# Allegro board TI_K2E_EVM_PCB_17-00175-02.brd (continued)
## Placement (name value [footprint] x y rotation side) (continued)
C819  100nF  [C0402]  131.32 21.34 270 bottom
C820  1nF  [C0402]  106.43 19.56 0 bottom
C821  560pF  [CC0201_IPC7351_EINF]  96.39 19.43 90 bottom
C822  22pF  [C0402]  104.65 18.92 270 bottom
C823  22pF  [C0402]  98.08 18.85 90 bottom
C824  100nF  [C0402]  20.95 18.8 0 bottom
C825  10uF  [C0603]  22.61 18.67 0 bottom
C826  22uF  [C0805]  24.77 17.4 180 bottom
C827  10uF  [C0603]  142.62 17.02 270 bottom
C828  100uF  [CC1210]  28.19 16.13 90 bottom
C829  10nF  [C0402]  102.87 16.05 180 bottom
C830  10nF  [C0402]  100.08 16.05 180 bottom
C831  1nF  [C0402]  153.42 16 180 bottom
C832  10nF  [C0402]  151.89 16 180 bottom
C833  100nF  [C0402]  150.37 16 180 bottom
C834  100nF  [C0402]  139.98 15.9 180 bottom
C835  100nF  [C0402]  147.45 14.28 0 bottom
C836  100nF  [C0402]  144.4 14.61 0 bottom
C837  10uF  [C0603]  142.75 14.61 0 bottom
C838  1uF  [C0402]  144.91 11.18 180 bottom
C839  100nF  [C0402]  143.51 11.18 180 bottom
C840  100nF  [C0402]  142.11 11.18 180 bottom
C841  4.7uF  [C0603]  146.56 10.79 180 bottom
C842  4.7nF  [C0402]  62.28 9.74 270 bottom
C843  10nF  [C0402]  104.01 9.4 270 bottom
C844  33pF  [C0402]  135.13 8.57 90 bottom
C845  33pF  [C0402]  132.97 8.57 270 bottom
C846  100nF  [C0402]  127.64 8.38 90 bottom
C847  100nF  [C0402]  131.06 8.06 180 bottom
C848  220nF  [C0402]  129.54 8.06 180 bottom
C849  2.2uF  [C0402]  59.56 7.24 270 top
C850  1uF  [C0402]  127.64 6.86 90 bottom
C851  6.8pf  [C0402]  97.16 6.1 90 bottom
C852  3.3uF  [C0603]  102.54 5.59 0 bottom
C853  4.7uF  [C0603]  100.84 5.59 0 bottom
C854  10uF  [C0603]  99.14 5.59 0 bottom
C855  10uF  [C0603]  127.64 5.08 90 bottom
C856  12pF  [C0402]  105.56 4.5 270 bottom
C857  100pF  [C0402]  66.42 4.19 0 bottom
C858  2.2nF  [C0402]  64.9 4.19 0 bottom
C859  2.2nF  [C0402]  62.1 4.19 0 bottom
C860  100nF  [C0402]  126.47 105.26 0 top
C861  100nF  [C0402]  127.89 106.81 0 top
C862  100nF  [C0402]  126.47 107.29 0 top
C863  100nF  [C0402]  125.96 103.61 90 top
C864  100nF  [C0402]  127.89 104.78 0 top
C865  100nF  [C0402]  123.91 109 90 top
C866  22uF  [C0805]  123.93 99.43 270 top
C872  10pF  [C0402]  12.7 35.94 270 bottom
C874  10pF  [C0402]  12.81 130.35 90 bottom
C875  100nF  [C0402]  141.22 119 270 bottom
C876  100nF  [C0402]  139.95 126.75 90 bottom
C881  100nF  [C0402]  146.18 21.59 90 bottom
C882  10uF  [C0603]  146.18 19.81 90 bottom
C883  100nF  [C0402]  141.35 22.86 180 bottom
C884  10uF  [C0603]  139.57 23.62 180 bottom
C885  100nF  [C0402]  158 10.09 180 bottom
C886  100nF  [C0402]  171.45 10.09 180 bottom
C887  10uF  [C0603]  160.02 9.58 180 bottom
C888  100nF  [C0402]  169.93 10.09 180 bottom
C889  100nF  [C0402]  169.54 22.33 90 bottom
C890  100nF  [C0402]  169.54 20.83 90 bottom
C891  10uF  [C0603]  163.83 30.38 0 bottom
C892  100nF  [C0402]  161.81 30 0 bottom
C893  100nF  [C0402]  42.55 91.69 90 bottom
C894  100nF  [C0402]  46.99 91.95 0 top
C895  100nF  [C0402]  148.21 27.81 0 bottom
C896  10pF  [C0402]  17.18 132.85 90 bottom
CN1  TSW-103-23-T-S  [BERG_1X3]  153.37 140.97 0 top
CN2  5223957-3  [POWERMODULE_2P_5223957-3]  27.5 140.75 270 top
CN3  FTSH-105-01-F-DV-K-P-TR  [SAMTECH_FTSH-105-01-F-DV-K-P-TR]  102.11 138.43 0 top
CN4  TSW-102-23-T-S  [SAMTSW-102-22-T-S]  134.54 123.19 180 top
CN5  TSW-106-23-T-S  [SAMTEC_TSW-106-23-T-S]  125.73 114.55 90 top
CN6  TSW-103-23-T-S  [BERG_1X3]  134.37 119 0 top
CN7  BB_60x2V_S0.5mm  [BB_60X2P_20_2225X285_F]  37.93 115.24 90 top
COM1  22-23-2041  [MOL22-23-2041]  167.06 122.05 270 top
COM2  22-23-2041  [MOL22-23-2041]  158.12 122.05 270 top
CT1  1000uF  [CT7343]  61.98 26.54 180 top
CT2  680uF  [CT7343]  61.98 21.34 180 top
CT3  1000uF  [CT7343]  61.98 16.13 180 top
CT4  100uF  [CT7343]  50.01 12.7 90 top
CT5  100uF  [CT7343]  44.81 12.7 90 top
CT6  100uF  [CT7343]  86.36 10.92 270 top
CT7  100uF  [CT7343]  36.83 9.53 270 top
CT8  220uF  [C_2P_114_138X118]  110.34 36.93 90 bottom
CVDD  Test Point  [TP365X205]  73.15 22.35 0 top
CVDD1  Test Point  [TP-S40]  83.95 22.73 0 top
D1  PMEG1020EH  [DIODE_2P_146_106X61_ANODE2]  126.87 146.05 90 top
D2  PMEG1020EH  [DIODE_2P_146_106X61_ANODE2]  126.87 143.76 90 top
D3  KPA-1606EC  [LED_2P_KPA-1606EC]  178.9 129.12 270 top
D4  KPA-1606QBC-D  [LED_2P_KPA-1606QBC-D]  178.9 125.84 270 top
D5  KP-1608EC  [LED_0603]  179.2 112.9 270 top
D6  KP-1608MGC  [LED_0603]  179.2 109.81 90 top
D7  GREEN  [LED603-35X45-REV]  177.25 109.6 270 top
D8  GREEN  [LED603-35X45-REV]  175.14 109.6 270 top
D9  GREEN  [LED603-35X45-REV]  173.02 109.6 270 top
D10  LED  [LED_LTST-C171]  48.51 25.53 180 top
D11  B340A-13-F  [DIODE_2P_158_197X110]  13.97 17.91 90 top
D12  SMBJ12A  [DIO_DO214AA_SMB]  32.13 9.14 90 top
D13  TPD4S012DRYR  [SON_6P_20_59X39]  167.77 135.94 270 bottom
D14  TPD4S012DRYR  [SON_6P_20_59X39]  166.62 100.72 270 bottom
D15  B340A-13-F  [DIODE_2P_158_197X110]  62.38 32.69 0 bottom
DBG_D1  KPBA-3010ESGC  [LED_2P_KPBA-3010ESGC]  178.51 121.69 90 top
DBG_D2  SML-LX0402USBC-TR  [LED_SML-LX0402]  179.2 117.99 90 top
DBG_D3  SML-LX0402USBC-TR  [LED_SML-LX0402]  179.2 115.62 90 top
DIMM1  2013289-1_DDR3-SODIMM_204P  [TYCO2013289-2_DDR3]  97.54 92.57 90 top
EEPROM1  M24M01-RMN6TP  [SOIC_8P_50_193X236]  117.22 75.31 270 bottom
EMU1  BB_60V_S0.5mm  [BB_30X2P_20_838X285_F]  96.77 116.72 270 top
ESD1  -  [AMC-ESD-B]  160 146.15 0 top
F1  RGEF600-2  [PTC_RUEF300]  25.7 5.48 90 top
FAN1  22-23-2041  [MOL22-23-2041]  83.14 29.58 0 top
FB1  220_100MHz  [L0805]  111.18 138.46 90 top
FB2  120_100MHz  [L0402]  129.46 130.18 90 top
FB3  120_100MHz  [L0402]  108.2 122.66 270 top
FB4  220_100MHz  [L0805]  168.53 93.47 90 top
FB5  220_100MHz  [L0805]  142.75 92.33 270 top
FB6  30_100MHz  [L0805]  174.5 50.04 90 top
FB7  120_100MHz  [L0402]  24.13 37.97 270 top
FB8  120_100MHz  [L0402]  176.02 32.51 0 top
FB9  120_100MHz  [L0402]  29.72 29.34 0 top
FB10  120_100MHz  [L0402]  42.93 28.32 180 top
FB11  120_100MHz  [L0402]  35.69 26.92 90 top
FB12  30_100MHz  [L0805]  25.45 24.84 90 top
FB13  120_100MHz  [L0402]  172.25 141.48 180 bottom
FB14  220_100MHz  [L0805]  168.78 132.33 270 bottom
FB15  BLM31PG500SN1L  [INDC1206]  162.1 107.42 0 bottom
FB16  120_100MHz  [L0402]  176.82 106.9 0 bottom
FB17  0.47uF  [FIL_NFM21PC]  163.45 98.93 180 bottom
FB18  0.47uF  [FIL_NFM21PC]  162.69 94.49 180 bottom
FB19  0.47uF  [FIL_NFM21PC]  148.65 87.63 90 bottom
FB20  120_100MHz  [L0402]  61.34 85.19 0 bottom
FB21  470_100MHz  [L0402]  75.31 83.69 90 bottom
FB22  120_100MHz  [L0402]  71.88 82.68 90 bottom
FB23  120_100MHz  [L0402]  32 81.53 90 bottom
FB24  470_100MHz  [L0402]  38.76 80.14 90 bottom
FB25  120_100MHz  [L0402]  32.51 76.2 90 bottom
FB26  470_100MHz  [L0402]  32.61 70.76 270 bottom
FB27  120_100MHz  [L0402]  31.88 65.53 90 bottom
FB28  100_100MHz  [L0402]  80.9 62.87 0 bottom
FB29  120 OHM_100Mhz  [L0402]  33.15 59.44 270 bottom
FB30  120_100MHz  [L0402]  38.1 58.24 180 bottom
FB31  120 OHM_100Mhz  [L0402]  33.15 52.53 270 bottom
FB32  120_100MHz  [L0402]  148.82 38.33 270 bottom
FB33  120_100MHz  [L0402]  34.92 26.92 90 bottom
FB34  120_100MHz  [L0402]  151.38 20.83 0 bottom
FB35  120_100MHz  [L0402]  145.92 14.61 270 bottom
FM1  Fiducial  [FIDUCIAL]  21.98 36.32 0 top
FM2  Fiducial  [FIDUCIAL]  21.98 36.32 180 bottom
FM3  Fiducial  [FIDUCIAL]  147.78 4.98 0 top
FM4  Fiducial  [FIDUCIAL]  147.78 4.98 180 bottom
FM5  Fiducial  [FIDUCIAL]  157.66 136.8 0 top
FM6  Fiducial  [FIDUCIAL]  157.66 136.8 180 bottom
GND1  Test Point  [TP-S40]  24.51 27.56 0 top
GND2  Test Point  [TP-S40]  155.57 45.97 0 top
GND3  Test Point  [TP-S40]  152.27 129.41 0 top
GND4  Test Point  [TP-S40]  45.34 118.62 0 top
GNDC  Test Point  [TP365X205]  50.16 19.56 0 top
H1  -  [H35-NPTH]  157.1 132.72 0 top
H2  -  [H35-NPTH]  29.34 132.33 0 top
H3  -  [H35-NPTH]  42.42 24.64 0 top
H4  H107x17-NPTH  [H107X17-NPTH]  159 4.8 0 top
H5  -  [H35-NPTH]  168.78 4.19 0 top
H6  -  [H27P35-MTH]  176.85 3.25 0 top
J1  54819-0519  [MOL54819-0519]  171.8 134.91 90 top
J2  ATCA  [ATCA_160P_384312]  7.9 122.85 270 top
J3  54819-0519  [MOL54819-0519]  171.8 99.7 90 top
J4  ATCA  [ATCA_160P_384312]  7.9 97.85 270 top
J5  HEADER 10X2 CTI-20  [SAMFTR-110-03-G-D-LC]  159.35 90.3 270 top
J6  KMMXAB10SMT4SB30  [KYCON_KMMXAB10SMT4SB30]  175.07 56.19 90 top
J7  USB3.0_9H  [USB_9P_UEA1112C-4HK1-4H]  168.62 41.13 90 top
J8  280371-2  [TE_280371-2]  19 25.78 270 top
J9  XMH-TRJG17020AENL  [XMULTIPLE_XMH-TRJG17020AENL]  165.09 16.75 90 top
J10  0678005001  [MOL67800-5005]  36.64 19.96 0 top
J11  PJ-044BH  [CUI_PJ-044BH]  18.38 4.11 180 top
L1  LQM2HPN2R2MJ0L  [IND1008]  139.7 78.36 180 top
L2  1.2uH,11.1A  [IND_XAL5030-222MEB]  148.11 70.01 180 top
L3  ACM2012-900-2P-TL  [ACM2012]  167.89 63 0 top
L4  ACM2012-900-2P-TL  [ACM2012]  167.89 61.1 0 top
L5  ACM2012-900-2P-TL  [ACM2012]  167.89 59.19 0 top
L6  2.2uH,5A  [IND_VLCF5020T]  150.57 57.62 270 top
L7  ACM2012-900-2P-TL  [ACM2012]  158.5 41.21 0 bottom
L8  ACM2012-900-2P-TL  [ACM2012]  158.5 43.31 0 bottom
L9  ACM2012-900-2P-TL  [ACM2012]  158.5 39.12 0 bottom
L10  2.2uH,5A  [IND_VLCF5020T]  109.88 18.16 0 top
L11  2.2uH,5A  [IND_VLCF5020T]  91.95 16.89 0 top
L12  220nH,30.7A  [IND_IHLP3232DZERR47M01]  73.15 15.16 90 top
L13  3.3uH,4A  [IND_VLC5045T-100M]  109.88 7.57 180 top
L14  3.3uH,4A  [IND_VLC5045T-100M]  92.2 7.49 180 top
LCD1  NHD-C12832A1Z-FSB-FBW-3V3  [LCD_17P_NHD-C12832A1Z]  65.91 134.11 180 top
NOR1  N25Q128A11ESF40F  [SOIC127P1032_16]  144.17 46.2 0 top
NOREF  -  []  0 3.81 0 top
NOREF#2  -  []  176.85 3.25 0 top
NOREF#3  -  []  157.1 132.72 90 top
NOREF#4  -  []  6.7 144.2 0 top
NOREF#5  -  []  0 3.81 0 top
NOREF#6  -  []  180.6 1.1 90 top
NOREF#7  -  []  0 36.75 0 top
NOREF#8  -  []  158 0 90 top
NOREF#9  -  []  29.34 132.33 90 top
NOREF#10  -  []  122.33 179.27 180 bottom
OSC1  32.768KHz  [OSCCC200X250X70-4N]  152.4 132.59 180 top
PMBUS1  TSW-105-23-T-S  [HD_5X1P_100_D]  130.05 120.14 90 top
Q1  MCP9700AT-E/LT  [SC-70_5P]  114.55 139.92 0 top
Q2  TLV1117-33CDCY  [SOT-223]  125.73 137.54 0 top
Q3  2N3904  [SOT-23]  174.88 128.14 90 top
Q4  2N3904  [SOT-23]  174.75 123.19 90 top
Q5  2N3904  [SOT-23]  174.75 118.36 90 top
Q6  2N3904  [SOT-23]  174.75 113.79 90 top
Q7  NTA4153N  [SOT416_3P]  170.81 109.56 0 top
Q8  NTA4153N  [SOT416_3P]  166.75 109.56 0 top
Q9  PBSS5120T,215  [SOT23]  44.83 33.53 90 top
Q10  APL431LBAI-TRG  [SOT-23]  67.58 141.09 0 bottom
Q11  2N3904  [SOT-23]  174.88 128.14 270 bottom
Q12  2N3904  [SOT-23]  174.75 123.19 270 bottom
Q13  2N3904  [SOT-23]  174.75 118.36 270 bottom
Q14  2N3904  [SOT-23]  174.75 113.79 270 bottom
Q15  TPS73701DRBT  [QFN_8P_26_118X118]  145.16 24.51 90 bottom
R1  10M  [R1206]  153.03 145.29 270 top
R2  10M  [R1206]  38.48 145.29 90 top
R3  0E  [R0402]  164.47 143.51 90 top
R4  0E  [R0402]  163.07 143.51 90 top
R5  33K  [R0402]  149.86 141.99 0 top
R6  4.7K  [R0402]  162.56 140.46 270 top
R7  0E  [R0402]  149.86 139.45 0 top
R8  33K  [R0402]  149.86 137.92 0 top
R9  10K  [R0402]  153.37 136.96 270 top
R10  10K  [R0402]  149.86 136.4 180 top
R11  0E  [R0402]  120.02 135.51 90 top
R12  0E  [R0402]  118.49 135.51 90 top
R13  10K  [R0402]  116.59 135.51 270 top
R14  10K  [R0402]  115.06 135.51 270 top
R15  10K  [R0402]  113.54 135.51 270 top
R16  0E  [R0402]  149.86 135 0 top
R17  0E  [R0402]  121.67 134.62 0 top
R18  3K  [RC0201_IPC7351_EINF]  109.22 133.76 180 top
R19  0E  [R0402]  121.41 133.22 180 top
R20  0E  [R0402]  105.97 132.97 0 top
R21  1.3K  [R0402]  109.22 132.21 180 top
R22  22E  [R0402]  149.61 131.7 0 top
R23  0E  [R0402]  121.41 131.7 180 top
R24  10K  [R0402]  105.97 131.58 0 top
R25  0E  [R0402]  109.22 130.68 180 top
R26  0E  [R0402]  121.41 130.18 0 top
R27  510E  [R0402]  173.23 130.05 0 top
R28  10K  [R0402]  149.61 130.05 180 top
R29  0E  [R0402]  109.22 129.29 180 top
R30  0E  [R0402]  121.41 128.65 180 top
R31  4.7K  [R0402]  102.62 128.52 180 top
R32  49.9E  [R0402]  177.42 127.87 270 top
R33  90.9K  [R0402]  109.22 127.76 180 top
R34  0E  [R0402]  31.81 127.76 180 top
R35  4.7K  [R0402]  29.84 127.76 180 top
R36  0E  [R0402]  121.41 127.13 180 top
R37  10E  [R0402]  102.62 127.13 180 top
R38  10K  [R0402]  138.19 126.67 270 top
R39  0E  [R0402]  136.14 126.62 90 top
R40  0E  [R0402]  134.62 126.62 90 top
R41  0E  [R0402]  109.22 126.36 180 top
R42  0E  [R0402]  30.86 126.36 180 top
R43  0E  [R0402]  121.41 125.73 0 top
R44  4.7K  [R0402]  102.62 125.73 180 top
R45  100E  [R0402]  90.83 125.35 0 top
R46  100E  [R0402]  88.27 125.35 180 top
R47  120E  [R0402]  177.55 125.22 90 top
R48  510E  [R0402]  173.1 124.97 0 top
R49  0E  [R0402]  109.22 124.97 180 top
R50  33E  [R0402]  121.41 124.33 0 top
R51  10E  [R0402]  102.62 124.33 180 top
R52  10E  [R0402]  90.81 123.95 0 top
R53  4.7K  [R0402]  88.27 123.95 180 top
R54  22E  [R0402]  43.75 122.99 0 top
R55  0E  [R0402]  121.92 122.66 270 top
R56  0E  [R0402]  120.4 122.66 270 top
R57  0E  [R0402]  119 122.66 270 top
R58  0E  [R0402]  117.47 122.66 90 top
R59  0E  [R0402]  115.98 122.66 90 top
R60  0E  [R0402]  114.4 122.66 270 top
R61  0E  [R0402]  112.9 122.66 270 top
R62  0E  [R0402]  111.46 122.66 270 top
R63  0E  [R0402]  109.91 122.66 270 top
R64  4.7K  [R0402]  102.87 122.56 0 top
R65  10E  [R0402]  90.81 122.56 0 top
R66  4.7K  [R0402]  88.27 122.56 180 top
R67  0E  [R0402]  102.87 121.16 0 top
R68  0E  [R0402]  90.81 121.16 0 top
R69  49.9E  [R0402]  176.66 120.14 180 top
R70  510E  [R0402]  173.1 120.14 0 top
R71  120E  [R0402]  177.55 118.54 180 top
R72  10K  [R0402]  142.62 116.97 270 top
R73  120E  [R0402]  177.42 116.17 180 top
R74  1K  [R0402]  68.96 116.15 0 top
R75  510E  [R0402]  173.1 115.44 0 top
R76  2.2K  [R0402]  140.72 115.06 0 top
R77  2.2K  [R0402]  138.68 115.06 0 top
R78  2.2K  [R0402]  136.53 115.06 180 top
R79  22E  [R0402]  145.8 113.92 270 top
R81  22E  [R0402]  153.54 113.92 270 top
R82  22E  [R0402]  151.89 113.92 270 top
R83  22E  [R0402]  150.37 113.92 270 top
R84  470E  [R0402]  148.84 113.92 90 top
R85  470E  [R0402]  147.37 113.92 90 top
R87  2.2K  [R0402]  133.73 113.92 180 top
R88  4.7K  [R0402]  61.85 114.02 180 top
R89  120E  [R0402]  177.42 113.65 180 top
R90  2.2K  [R0402]  140.72 113.54 180 top
R91  2.2K  [R0402]  138.68 113.54 180 top
R92  2.2K  [R0402]  136.53 113.54 0 top
R93  0E  [R0402]  68.89 113.23 180 top
R94  0E  [R0402]  80.64 112.89 90 top
R95  4.7K  [R0402]  61.85 112.62 0 top
R96  2.2K  [R0402]  133.73 112.39 0 top
R97  10K  [R0402]  155.96 111.25 180 top
R98  470E  [R0402]  133.73 110.87 180 top
R99  4.7K  [R0402]  61.5 110.11 90 top
R100  4.7K  [R0402]  102.36 109.97 0 top
R101  10K  [R0402]  155.96 109.73 180 top
R102  470E  [R0402]  133.73 109.35 180 top
R103  2.2K  [R0402]  168.78 108.31 270 top
R104  2.2K  [R0402]  164.72 108.31 270 top
R105  47E  [R0402]  155.96 108.2 0 top
R106  470E  [R0402]  133.73 107.7 180 top
R107  470E  [R0402]  133.73 106.17 180 top
R108  0E  [R0402]  67.06 104.78 270 top
R109  4.7K  [R0402]  93.98 104.65 90 top
R110  10K  [R0402]  133.73 104.39 180 top
R111  1K  [R0402]  131.57 104.39 0 top
R112  0E  [R0402]  85.12 101.15 90 bottom
R113  10K  [R0402]  81.89 103.63 270 top
R114  10K  [R0402]  162.43 103 0 top
R115  470E  [R0402]  120.76 101.15 270 top
R116  470E  [R0402]  120.75 103 270 top
R117  470E  [R0402]  119.35 103 270 top
R118  10K  [R0402]  117.96 103 270 top
R119  470E  [R0402]  116.56 103 270 top
R120  470E  [R0402]  115.16 103 270 top
R121  470E  [R0402]  113.77 103 270 top
R122  0E  [R0402]  112.37 103 270 top
R123  0E  [R0402]  110.97 103 270 top
R124  470E  [R0402]  109.58 103 270 top
R125  10K  [R0402]  133.73 102.74 180 top
R126  1K  [R0402]  131.57 102.74 0 top
R127  4.7K  [R0402]  99.69 102.62 90 top
R128  10E  [R0402]  98.17 102.62 270 top
R129  10E  [R0402]  96.77 102.62 90 top
R130  10E  [R0402]  95.38 102.62 90 top
R131  10E  [R0402]  93.98 102.62 90 top
R132  10E  [R0402]  92.46 102.62 270 top
R133  499E  [R0603]  65.15 102.11 180 top
R134  402E  [R0603]  85.32 101.85 180 top
R135  0E  [R0402]  77.95 101.6 270 top
R136  10K  [R0402]  63.5 101.6 90 top
R137  10K  [R0402]  61.98 101.6 90 top
R138  0E  [R0402]  59.94 101.6 270 top
R139  10K  [R0402]  81.89 101.47 90 top
R140  22E  [R0402]  162.43 101.35 0 top
R141  10K  [R0402]  133.73 101.09 180 top
R142  1K  [R0402]  131.57 101.09 0 top
R143  10E  [R0402]  98.04 100.33 90 top
R144  10E  [R0402]  96.65 100.33 90 top
R145  10E  [R0402]  95.25 100.33 90 top
R146  10E  [R0402]  93.85 100.33 270 top
R147  10E  [R0402]  92.46 100.33 90 top
R148  10K  [R0402]  133.73 99.44 180 top
R149  1K  [R0402]  131.57 99.44 0 top
R150  0E  [R0402]  77.72 99.06 0 top
R151  0E  [R0402]  59.69 98.09 0 top
R152  1K  [R0402]  133.73 97.79 0 top
R153  1K  [R0402]  131.57 97.79 0 top
R154  0E  [R0402]  77.7 97.66 0 top
R155  3.16K  [R0402]  75.54 97.66 180 top
R156  1.5K  [R0603]  155.83 97.16 0 top
R157  0E  [R0402]  59.69 96.52 0 top
R158  1K  [R0402]  133.73 96.14 0 top
R159  1K  [R0402]  131.57 96.14 0 top
R160  49.9E  [R0402]  77.7 96.14 180 top
R161  5.6K  [R0402]  75.54 96.14 0 top
R162  150K  [R0402]  168.15 95.45 180 top
R163  0E  [R0402]  59.69 94.74 0 top
R164  0E  [R0402]  59.69 93.13 0 top
R165  0E  [R0402]  44.96 92.71 270 top
R166  10K  [R0402]  150.88 91.62 270 top
R167  0E  [R0402]  59.69 91.61 0 top
R168  1K  [R0402]  138.51 91.59 270 top
R169  1K  [R0402]  137.03 91.59 270 top
R170  47E  [R0402]  135.38 91.57 90 top
R171  49.9E  [R0402]  77.7 91.57 180 top
R172  1K  [R0402]  44.96 90.68 270 top
R173  0E  [RC0201_IPC7351_EINF]  46.74 86.23 180 top
R174  0E  [RC0201_IPC7351_EINF]  46.74 85.09 180 top
R175  1K  [R0402]  138.51 89.43 90 top
R176  1K  [R0402]  137.03 89.43 90 top
R177  0E  [R0402]  79.92 88.25 90 top
R178  0E  [R0402]  78.49 88.25 90 top
R179  10K  [R0402]  170.36 87.9 0 top
R180  100K  [R0402]  145.54 86.84 180 top
R181  100E  [R0402]  170.36 86.37 180 top
R182  4.7K  [R0402]  53.72 86.36 90 top
R183  4.7K  [R0402]  52.32 86.36 90 top
R184  4.7K  [R0402]  50.8 86.36 90 top
R185  0E  [R0402]  144.15 84.58 180 top
R186  0E  [R0402]  19.05 84.33 270 top
R187  0E  [R0402]  17.4 84.33 270 top
R188  4.7K  [R0402]  15.88 84.33 90 top
R189  0E  [R0402]  14.35 84.33 270 top
R190  0E  [R0402]  12.7 84.33 270 top
R191  2.49K  [R0402]  138.94 83.95 180 top
R192  10K  [R0402]  138.94 82.55 180 top
R193  4.7K  [R0402]  13.21 82.17 180 top
R194  0E  [R0402]  149.35 81.46 90 top
R195  10K  [R0402]  138.94 81.15 180 top
R196  100K  [R0402]  147.57 80.9 180 top
R197  4.7K  [R0402]  22.99 80.77 180 top
R198  4.7K  [R0402]  13.21 80.77 180 top
R199  10.2K  [R0402]  147.57 79.5 180 top
R200  4.7K  [R0402]  22.99 79.38 180 top
R201  4.7K  [R0402]  13.21 79.38 180 top
R202  0E  [R0402]  147.45 77.72 90 top
R203  2.49K  [R0402]  146.05 77.72 270 top
R204  8.87K  [R0402]  157.25 75.47 0 top
R205  10K  [R0402]  168.38 75.28 0 top
R206  0E  [RC0201_IPC7351_EINF]  81.71 75.16 0 top
R207  10E  [R0402]  150.29 74.8 270 top
R208  768E  [R0603]  154.11 74.12 270 top
R209  10K  [R0402]  157.25 73.94 180 top
R210  0E  [RC0201_IPC7351_EINF]  81.71 73.89 0 top
R211  100E  [R0402]  168.38 73.75 180 top
R212  68.1K  [R0603]  156.92 66.85 270 top
R213  10K  [R0402]  154.6 66.85 270 top
R214  0E  [RC0201_IPC7351_EINF]  80.29 65.28 0 top
R215  10K  [R0402]  144.18 60.78 90 top
R216  53.6K  [R0402]  141.3 60.53 0 top
R217  2.2K  [R0402]  144.3 53.87 180 top
R218  10K  [R0402]  142.04 53.75 0 top
R219  53.6K  [R0402]  140 53.75 180 top
R220  0E  [R0402]  161.66 53.25 0 top
R221  10E  [R0402]  147.6 53.11 90 top
R222  4.7K  [R0402]  163.47 52.79 270 top
R223  0E  [R0402]  160.71 46.4 0 top
R224  10E  [R0402]  60.2 42.75 270 top
R225  10E  [R0402]  58.67 42.75 90 top
R226  10E  [R0402]  57.15 42.75 270 top
R227  10E  [R0402]  60.2 40.59 270 top
R228  10E  [R0402]  58.67 40.59 270 top
R229  10E  [R0402]  57.15 40.55 270 top
R230  1K  [R0402]  54.61 36.45 270 top
R231  4.7K  [R0402]  44.83 36.45 270 top
R232  22E  [R0402]  81.79 36.3 270 top
R233  22E  [R0402]  80.39 36.3 270 top
R234  22E  [R0402]  78.99 36.3 90 top
R235  22E  [R0402]  77.6 36.3 90 top
R236  0E  [RC0201_IPC7351_EINF]  92.71 36.3 270 top
R237  0E  [RC0201_IPC7351_EINF]  90.12 36.3 270 top
R238  0E  [R0402]  88.82 36.3 90 top
R239  4.7K  [R0402]  87.43 36.3 270 top
R240  4.7K  [R0402]  86.03 36.3 270 top
R241  4.7K  [R0402]  84.63 36.3 90 top
R242  4.7K  [R0402]  83.24 36.3 270 top
R243  0E  [R0402]  91.41 36.27 90 top
R244  4.7K  [R0402]  93.93 36.22 270 top
R245  4.7K  [R0402]  154.2 34.45 90 top
R246  0E  [R0402]  152.76 34.45 270 top
R247  4.7K  [R0402]  94.27 33.07 180 top
R248  100E  [R0402]  172.72 32.39 270 top
R249  100E  [R0402]  164.34 32.38 270 top
R250  6.04K  [R0402]  26.8 32.38 180 top
R251  4.7K  [R0402]  94.27 31.67 180 top
R252  4.7K  [R0402]  94.27 30.28 180 top
R253  4.7K  [R0402]  94.27 28.88 180 top
R254  2.2K  [R0402]  48.51 23.62 0 top
R255  0E  [R0402]  100.2 21.87 270 top
R256  2.7K  [R0402]  103.97 20.32 0 top
R257  2.49K  [R0402]  98.08 20.24 0 top
R258  0E  [R0402]  102.01 19.61 270 top
R259  0E  [R0402]  100.23 19.61 270 top
R260  43.2K  [R0402]  103.97 18.92 0 top
R261  13.7K  [R0402]  98.08 18.85 0 top
R262  10E  [R0805]  74.93 8.26 90 top
R263  0E  [R0402]  70.36 8.64 0 top
R264  100E  [R0402]  172.59 7.3 90 top
R265  100E  [R0402]  164.35 7.3 90 top
R266  14K  [R0402]  69.98 7.01 180 top
R267  1E  [R1206]  53.98 6.48 270 top
R268  127K  [R0402]  60.2 5.85 0 top
R269  13.7K  [R0402]  97.16 6.1 0 top
R270  6.98K  [R0402]  105.44 5.89 0 top
R271  14K  [R0402]  69.98 5.62 180 top
R272  10K  [R0402]  100.33 5.59 90 top
R273  43.2K  [R0402]  97.16 4.57 0 top
R274  8.87K  [R0402]  105.44 4.5 0 top
R275  20K  [R0402]  69.98 4.22 180 top
R276  0E  [R0402]  56.11 4.09 90 top
R277  0E  [R0402]  68.33 2.92 270 top
R278  10K  [R0402]  66.93 2.92 270 top
R279  6.81K  [R0402]  64.87 2.92 270 top
R280  10K  [R0402]  62.99 2.92 90 top
R281  0E  [R0402]  101.35 9.53 270 bottom
R282  10K  [R0402]  102.01 19.61 270 bottom
R283  22E  [R0402]  140.21 114.94 0 bottom
R284  0E  [R0402]  145.16 145.03 90 bottom
R285  3K  [RC0201_IPC7351_EINF]  143.64 145.03 270 bottom
R286  0E  [R0402]  142.11 145.03 90 bottom
R287  3K  [RC0201_IPC7351_EINF]  140.59 145.03 270 bottom
R288  0E  [R0402]  137.77 145.03 90 bottom
R289  3K  [RC0201_IPC7351_EINF]  136.25 145.03 270 bottom
R290  0E  [R0402]  134.59 145.03 90 bottom
R291  0E  [R0402]  132.94 145.03 90 bottom
R292  10K  [R0402]  131.29 145.03 90 bottom
R293  100E  [R0402]  97.46 144.91 90 bottom
R294  100E  [R0402]  94.92 144.91 90 bottom
R295  100E  [R0402]  92.38 144.91 90 bottom
R296  100E  [R0402]  89.84 144.91 90 bottom
R297  100E  [R0402]  113.54 144.27 270 bottom
R298  10K  [R0402]  112.01 144.27 90 bottom
R299  4.7K  [R0402]  115.11 143.92 90 bottom
R300  22E  [R0402]  108.46 143.22 90 bottom
R301  22E  [R0402]  106.93 143.22 90 bottom
R302  22E  [R0402]  105.41 143.22 90 bottom
R303  22E  [R0402]  103.89 143.22 90 bottom
R304  22E  [R0402]  102.36 143.22 90 bottom
R305  10K  [R0402]  100.84 143.22 90 bottom
R306  100E  [R0402]  69.66 142.44 180 bottom
R307  10K  [R0402]  117.14 142.01 0 bottom
R308  6.98K  [R0402]  64.45 140.97 90 bottom
R309  10K  [R0402]  62.92 140.97 90 bottom
R310  220E  [R0603]  83.19 139.32 180 bottom
R311  0E  [R0402]  102.11 138.3 270 bottom
R312  0E  [R0402]  131.32 136.78 0 bottom
R313  10K  [R0402]  97.46 136.66 270 bottom
R314  10K  [R0402]  92.38 136.66 270 bottom
R315  10K  [R0402]  89.84 136.66 270 bottom
R316  10K  [R0402]  94.92 136.54 270 bottom
R317  4.7K  [R0402]  136.91 136.4 270 bottom
R318  0E  [R0402]  131.32 135.38 0 bottom
R319  0E  [R0402]  131.32 133.99 0 bottom
R320  2K  [R0402]  109.22 133.76 0 bottom
R321  2K  [R0402]  109.22 132.21 0 bottom
R322  4.7K  [R0402]  149.86 131.57 0 bottom
R323  0E  [R0402]  109.22 129.29 180 bottom
R324  0E  [R0402]  121.41 128.65 180 bottom
R325  90.9K  [R0402]  109.22 127.76 0 bottom
R326  4.7K  [R0402]  149.86 127.38 0 bottom
R327  4.7K  [R0402]  169.8 127.13 180 bottom
R328  510E  [R0402]  173.23 126.36 0 bottom
R329  4.7K  [R0402]  55.75 126.01 0 bottom
R330  4.7K  [R0402]  66.67 125.98 180 bottom
R331  0E  [R0402]  156.59 123.57 270 bottom
R332  4.7K  [R0402]  155.19 123.57 90 bottom
R333  0E  [R0402]  153.8 123.57 270 bottom
R334  2.2K  [R0402]  117.47 122.66 90 bottom
R335  2.2K  [R0402]  115.98 122.66 90 bottom
R336  0E  [R0402]  114.43 122.66 270 bottom
R337  0E  [R0402]  112.9 122.66 270 bottom
R338  10K  [R0402]  109.91 122.66 90 bottom
R339  4.7K  [R0402]  168.78 121.6 90 bottom
R340  510E  [R0402]  173.1 121.28 0 bottom
R341  4.7K  [R0402]  102.87 121.16 180 bottom
R342  10K  [R0402]  146.3 120.27 180 bottom
R343  4.7K  [R0402]  86.11 119.25 90 bottom
R344  4.7K  [R0402]  84.58 119.25 270 bottom
R345  10K  [R0402]  146.3 118.87 180 bottom
R346  10K  [R0402]  151.64 118.75 180 bottom
R347  1K  [R0402]  109.6 117.65 180 bottom
R348  2.2K  [R0402]  146.3 117.6 180 bottom
R349  47E  [R0402]  119.33 117.47 90 bottom
R350  2.2K  [R0402]  113.13 117.47 90 bottom
R351  1K  [R0402]  111.58 117.47 90 bottom
R352  10K  [R0402]  151.64 117.09 180 bottom
R353  510E  [R0402]  173.1 116.64 0 bottom
R354  10K  [R0402]  109.6 116.08 0 bottom
R355  10K  [R0402]  151.64 115.7 180 bottom
R356  1K  [R0402]  109.6 114.68 180 bottom
R357  4.7K  [R0402]  95.87 114.12 180 bottom
R358  4.7K  [R0402]  164.97 114.05 270 bottom
R359  4.7K  [R0402]  163.58 114.05 90 bottom
R360  4.7K  [R0402]  156.34 121.6 270 bottom
R361  4.7K  [R0402]  159.89 113.92 90 bottom
R362  10K  [R0402]  153.54 113.92 270 bottom
R363  10K  [R0402]  151.89 113.92 90 bottom
R364  47E  [R0402]  121.03 113.28 0 bottom
R365  510E  [R0402]  172.85 112.14 0 bottom
R366  47E  [R0402]  121.03 111.89 180 bottom
R367  10K  [R0402]  109.6 111.76 180 bottom
R368  47E  [R0402]  155.96 111.25 0 bottom
R369  47E  [R0402]  121.03 110.49 180 bottom
R370  47E  [R0402]  109.6 110.24 180 bottom
R371  470E  [R0402]  177.17 109.73 90 bottom
R372  470E  [R0402]  175.14 109.73 90 bottom
R373  470E  [R0402]  173.02 109.73 90 bottom
R374  10K  [R0402]  157.99 109.73 180 bottom
R375  10K  [R0402]  155.96 109.73 0 bottom
R376  47E  [R0402]  120.9 109.09 180 bottom
R377  120E  [R0402]  178.75 108.97 180 bottom
R378  4.7K  [R0402]  89.92 108.58 180 bottom
R379  100E  [R0402]  155.96 108.2 180 bottom
R380  47E  [R0402]  109.6 107.31 180 bottom
R381  47E  [R0402]  155.57 106.3 270 bottom
R382  47E  [R0402]  120.14 106.05 270 bottom
R383  47E  [R0402]  109.6 105.92 180 bottom
R384  0E  [R0402]  170.18 105.72 270 bottom
R385  4.7K  [R0402]  101.9 105.16 180 bottom
R386  4.7K  [R0402]  91.67 103.76 0 bottom
R387  22E  [R0402]  101.9 101.26 180 bottom
R388  0E  [R0402]  45.73 100.01 180 bottom
R389  22E  [R0402]  101.9 99.96 180 bottom
R390  100K  [R0402]  51.1 95.22 0 bottom
R391  10E  [R0402]  59.56 93.73 90 bottom
R392  10E  [R0402]  57.78 93.73 90 bottom
R393  10E  [R0402]  55.88 93.73 90 bottom
R394  10E  [R0402]  53.85 93.73 90 bottom
R395  470E  [R0402]  156.46 93.6 90 bottom
R396  0E  [R0402]  154.94 93.6 90 bottom
R397  10K  [R0402]  153.42 93.6 90 bottom
R398  1.5K  [R0603]  151.64 92.58 180 bottom
R399  10E  [R0402]  60.58 91.69 90 bottom
R400  10E  [R0402]  58.67 91.69 90 bottom
R401  10E  [R0402]  56.77 91.69 90 bottom
R402  10E  [R0402]  54.86 91.69 90 bottom
R403  10E  [R0402]  52.83 91.69 90 bottom
R407  0E  [R0402]  45.21 96.65 180 bottom
R409  0E  [R0402]  159.26 88.27 0 bottom
R412  0E  [R0402]  41.66 93.85 90 bottom
R414  22E  [R0402]  50.42 85.04 180 bottom
R415  12.1K  [R0402]  161.67 84.3 0 bottom
R416  22E  [R0402]  46.86 83.95 90 bottom
R417  24.3K  [R0402]  161.67 82.78 180 bottom
R418  1K  [R0402]  73.28 82.68 90 bottom
R419  0E  [RC0201_IPC7351_EINF]  55.32 78.61 90 bottom
R420  0E  [RC0201_IPC7351_EINF]  54.05 78.61 90 bottom
R421  4.7K  [R0402]  122.17 77.6 180 bottom
R422  4.7K  [R0402]  122.17 75.95 0 bottom
R423  4.7K  [R0402]  112.27 75.56 0 bottom
R424  0E  [R0402]  83.92 75.46 180 bottom
R425  4.7K  [R0402]  122.17 74.42 0 bottom
R426  0E  [R0402]  83.92 74.07 180 bottom
R427  0E  [RC0201_IPC7351_EINF]  42.04 74.04 180 bottom
R428  4.7K  [R0402]  137.16 50.8 90 top
R429  4.7K  [R0402]  122.17 72.9 180 bottom
R430  0E  [RC0201_IPC7351_EINF]  42.04 72.9 180 bottom
R431  1K  [R0402]  61.47 72.62 270 bottom
R432  10K  [R0402]  83.85 72.47 0 bottom
R433  0E  [RC0201_IPC7351_EINF]  43.18 71.63 180 bottom
R434  3K  [RC0201_IPC7351_EINF]  51.98 71.36 0 bottom
R435  4.7K  [R0402]  112.27 71.25 0 bottom
R436  200E  [RC0201_IPC7351_EINF]  61.59 70.48 90 bottom
R437  0E  [RC0201_IPC7351_EINF]  43.18 70.36 180 bottom
R438  200E  [RC0201_IPC7351_EINF]  58.78 70.16 90 bottom
R439  475E  [R0402]  23.57 69.98 180 bottom
R440  4.7K  [R0402]  112.27 69.39 0 bottom
R441  3K  [RC0201_IPC7351_EINF]  53.18 69.36 270 bottom
R442  10K  [R0402]  16.08 69.22 90 bottom
R443  4.7K  [R0402]  136.65 45.21 270 top
R444  1.2K  [R0402]  14.55 68.09 90 bottom
R445  0E  [RC0201_IPC7351_EINF]  67.58 67.76 270 bottom
R446  3K  [RC0201_IPC7351_EINF]  53.58 67.36 0 bottom
R447  22E  [R0402]  136.65 43.69 180 top
R448  100E  [R0402]  16.08 67.07 90 bottom
R449  3K  [RC0201_IPC7351_EINF]  52.38 66.96 90 bottom
R450  150E  [R0402]  27.89 66.2 270 bottom
R451  10K  [R0402]  14.55 66.06 90 bottom
R452  33E  [R0402]  26.11 65.82 0 bottom
R453  4.7K  [R0402]  151.26 40.51 90 top
R454  240E  [RC0201_IPC7351_EINF]  69.98 65.36 270 bottom
R455  100E  [R0402]  29.41 65.12 90 bottom
R456  100E  [R0402]  16.08 65.12 90 bottom
R457  33E  [R0402]  26.11 64.42 0 bottom
R458  150E  [R0402]  27.89 64.04 90 bottom
R459  4.7K  [R0402]  122.17 63.96 180 bottom
R460  3K  [RC0201_IPC7351_EINF]  53.98 63.76 270 bottom
R461  0E  [RC0201_IPC7351_EINF]  39.04 63.5 180 bottom
R462  10K  [R0402]  25.86 62.87 0 bottom
R463  10K  [R0402]  23.7 62.87 180 bottom
R464  10K  [R0402]  21.54 62.87 0 bottom
R465  240E  [RC0201_IPC7351_EINF]  71.58 62.16 270 bottom
R466  4.7K  [R0402]  122.17 62.1 180 bottom
R467  240E  [RC0201_IPC7351_EINF]  71.18 60.16 0 bottom
R468  2.2K  [R0402]  113.68 60.07 0 bottom
R469  4.7K  [R0402]  79.76 58.42 0 bottom
R470  2.2K  [R0402]  113.68 58.22 0 bottom
R471  200K  [R0402]  120.78 57.54 0 bottom
R472  3K  [RC0201_IPC7351_EINF]  51.58 56.56 90 bottom
R473  0E  [RC0201_IPC7351_EINF]  42.93 55.5 180 bottom
R474  2.2K  [R0402]  113.68 54.23 0 bottom
R475  4.7K  [R0402]  16.13 53.98 180 bottom
R476  22E  [R0402]  140.21 113.54 0 bottom
R477  0E  [RC0201_IPC7351_EINF]  66.38 52.96 180 bottom
R478  0E  [RC0201_IPC7351_EINF]  67.58 52.56 270 bottom
R479  3K  [RC0201_IPC7351_EINF]  51.58 52.56 270 bottom
R480  2.2K  [R0402]  113.68 52.37 0 bottom
R481  22E  [R0402]  140.21 116.33 0 bottom
R482  4.7K  [R0402]  16.13 52.07 0 bottom
R483  22E  [R0402]  26.92 51.82 180 bottom
R484  200K  [R0402]  120.78 51.69 0 bottom
R485  0E  [R0402]  12.7 50.93 0 bottom
R486  100E  [R0402]  16.41 50.39 90 bottom
R487  22E  [R0402]  26.92 50.29 180 bottom
R488  1K  [R0402]  39.62 50.04 90 bottom
R489  0E  [R0402]  12.7 49.53 0 bottom
R490  0E  [R0402]  12.7 48.13 0 bottom
R491  4.7K  [R0402]  112.27 47.37 0 bottom
R492  0E  [R0402]  12.7 46.74 0 bottom
R493  4.7K  [R0402]  122.17 46.35 0 bottom
R494  4.7K  [R0402]  112.27 45.52 0 bottom
R495  22E  [R0402]  27.43 45.47 180 bottom
R496  10K  [R0402]  138.18 45.1 90 bottom
R497  4.7K  [R0402]  122.17 44.65 0 bottom
R498  0E  [R0402]  142.57 43.97 90 bottom
R499  22E  [R0402]  27.43 43.94 180 bottom
R500  0E  [R0402]  128.3 43.87 180 bottom
R501  100E  [R0402]  16.13 43.81 90 bottom
R502  10E  [R0402]  61.98 42.75 270 bottom
R503  10E  [R0402]  60.58 42.75 270 bottom
R504  10E  [R0402]  59.18 42.75 270 bottom
R505  10E  [R0402]  57.78 42.75 270 bottom
R506  4.7K  [R0402]  56.39 42.75 90 bottom
R507  0E  [R0402]  128.3 42.44 180 bottom
R508  0E  [R0402]  142.77 41.73 0 bottom
R509  0E  [R0402]  128.3 41.02 180 bottom
R510  10K  [R0402]  33.27 40.39 270 bottom
R511  0E  [R0402]  31.88 40.39 270 bottom
R512  0E  [R0402]  30.48 40.39 270 bottom
R513  4.7K  [R0402]  16.13 39.85 0 bottom
R514  0E  [R0402]  128.3 39.6 180 bottom
R515  0E  [R0402]  128.3 38.18 180 bottom
R516  10E  [R0402]  61.72 38.1 90 bottom
R517  10E  [R0402]  60.2 38.1 270 bottom
R518  10E  [R0402]  58.67 38.1 270 bottom
R519  10E  [R0402]  57.15 38.1 270 bottom
R520  10E  [R0402]  55.63 38.1 90 bottom
R521  0E  [RC0201_IPC7351_EINF]  86.64 37.47 270 bottom
R522  0E  [R0402]  85.24 37.47 270 bottom
R523  22E  [R0402]  83.85 37.46 90 bottom
R524  22E  [R0402]  82.45 37.47 270 bottom
R525  22E  [R0402]  81.05 37.47 270 bottom
R526  22E  [R0402]  79.65 37.47 270 bottom
R527  22E  [R0402]  78.26 37.46 90 bottom
R528  4.7K  [R0402]  88.04 37.34 270 bottom
R529  10K  [R0402]  123.47 37.11 180 bottom
R530  0E  [R0402]  128.32 36.78 180 bottom
R531  22E  [R0402]  39.75 36.32 0 bottom
R532  10K  [R0402]  123.47 35.59 0 bottom
R533  0E  [R0402]  148.41 35.53 270 bottom
R534  0E  [RC0201_IPC7351_EINF]  88.16 34.92 270 bottom
R535  22E  [R0402]  39.75 34.92 0 bottom
R536  4.7K  [R0402]  86.64 34.8 270 bottom
R537  4.7K  [R0402]  85.24 34.8 270 bottom
R538  22E  [R0402]  83.85 34.8 90 bottom
R539  22E  [R0402]  82.45 34.8 270 bottom
R540  22E  [R0402]  81.05 34.8 270 bottom
R541  22E  [R0402]  79.65 34.75 270 bottom
R542  22E  [R0402]  78.26 34.8 270 bottom
R543  22E  [R0402]  39.75 33.53 0 bottom
R544  100E  [RC0201_IPC7351_EINF]  72.39 87.25 180 top
R545  10E  [RC0201_IPC7351_EINF]  74.17 87.25 180 top
R546  100E  [RC0201_IPC7351_EINF]  72.39 88.52 0 top
R547  10E  [RC0201_IPC7351_EINF]  74.17 88.52 180 top
R548  22E  [R0402]  39.75 32.13 0 bottom
R549  1K  [R0402]  121.44 31.9 90 bottom
R550  1K  [R0402]  119.91 31.9 90 bottom
R551  4.99K  [R0402]  140.34 31.83 270 bottom
R552  10K  [R0402]  39.75 30.73 0 bottom
R553  1M  [R0402]  135 30.68 180 bottom
R554  1M  [R0402]  25.91 30.61 270 bottom
R555  1M  [R0402]  25.91 28.57 270 bottom
R556  0E  [R0402]  151.51 23.88 180 bottom
R557  10K  [R0402]  136.14 21.46 90 bottom
R558  0E  [R0402]  139.57 21.02 90 bottom
R559  0E  [R0402]  126.36 20.83 180 bottom
R560  26.1K  [R0402]  104.65 20.45 0 bottom
R561  28.7K  [R0402]  98.08 20.24 180 bottom
R562  0E  [R0402]  126.36 19.3 180 bottom
R563  0E  [R0402]  139.95 19.24 0 bottom
R564  0E  [R0402]  126.36 17.78 180 bottom
R566  10K  [R0402]  104.7 16.59 180 bottom
R567  10K  [R0402]  101.09 17.6 0 bottom
R568  0E  [R0402]  126.36 16.26 180 bottom
R569  383K  [R0402]  101.47 16.05 270 bottom
R570  0E  [R0402]  148.84 16 270 bottom
R571  0E  [R0402]  126.36 14.73 180 bottom
R572  0E  [R0402]  126.36 13.21 180 bottom
R573  0E  [R0402]  12.95 12.45 0 bottom
R574  0E  [R0402]  12.95 11.05 0 bottom
R575  0E  [R0402]  104.01 6.99 90 bottom
R576  4.99K  [R0402]  138.3 8.19 270 bottom
R577  0E  [R0402]  69.98 7.75 180 bottom
R578  10K  [R0402]  14.12 7.34 0 bottom
R579  1M  [R0402]  132.97 7.05 180 bottom
R580  0E  [R0402]  69.98 6.35 180 bottom
R581  10K  [R0402]  14.12 5.97 0 bottom
R582  54.9K  [R0402]  105.56 5.89 180 bottom
R583  0E  [R0402]  72.14 4.95 180 bottom
R584  0E  [R0402]  69.98 4.95 180 bottom
R585  10K  [R0402]  14.12 4.6 0 bottom
R586  100K  [R0402]  97.16 4.57 0 bottom
R587  6.81K  [R0402]  60.83 4.19 90 bottom
R588  0E  [R0402]  57.78 4.09 270 top
R589  0E  [R0402]  69.98 3.56 180 bottom
R590  215K  [R0402]  51.92 3.29 90 bottom
R591  10K  [R0402]  14.12 3.07 0 bottom
R592  8.45K  [R0402]  65.28 2.41 0 bottom
R593  93.1K  [R0402]  62.48 2.41 0 bottom
R594  2K  [R0402]  60.45 2.41 180 bottom
R595  10K  [R0402]  14.12 1.7 0 bottom
R596  22E  [R0402]  148.5 113.85 270 bottom
R597  22E  [R0402]  149.9 113.85 270 bottom
R598  10K  [R0402]  149.51 115.77 90 bottom
R599  22E  [R0402]  140.21 110.74 0 bottom
R600  22E  [R0402]  140.21 112.14 0 bottom
R601  49.9E  [R0402]  81.25 89.15 90 top
R602  49.9E  [R0402]  77.17 89.15 90 top
R603  0E  [R0402]  61.34 3.94 0 top
R604  4.7K  [R0402]  98.68 16.05 90 bottom
R605  4.7K  [R0402]  97.54 10.22 270 bottom
R606  4.7K  [R0402]  103.81 11.96 270 bottom
R607  4.7K  [R0402]  104.09 14.27 0 bottom
R608  4.7K  [R0402]  68.33 2.92 270 bottom
R609  4.7K  [R0402]  145.16 56.71 270 bottom
R610  4.7K  [R0402]  153.42 70.92 90 bottom
R611  0E  [R0402]  55.91 3.17 90 bottom
R612  0E  [R0402]  57.3 3.17 270 bottom
R613  0E  [R0402]  167 141.1 270 top
R614  0E  [R0402]  168.4 141.1 270 top
R615  0E  [R0402]  168.15 137.92 0 bottom
R621  100E  [R0402]  12.7 37.34 0 bottom
R623  100E  [R0402]  10.65 130.35 0 bottom
R624  1K  [R0402]  41.4 95.89 90 bottom
R625  1K  [R0402]  43.18 96.65 180 bottom
R626  4.7K  [R0402]  51.1 95.22 0 top
R627  4.7K  [R0402]  43.56 94.49 90 top
R628  0E  [R0402]  142.37 124.97 270 bottom
R629  33E  [R0402]  39.37 76.71 180 bottom
R630  33E  [R0402]  39.37 75.31 180 bottom
R631  0E  [R0402]  43.69 84.71 90 bottom
R632  0E  [R0402]  42.29 84.71 90 bottom
R634  33E  [R0402]  51.56 92.15 90 bottom
R635  33E  [R0402]  49.91 90.81 0 bottom
R636  33E  [R0402]  51.94 89.28 0 bottom
R637  33E  [R0402]  49.91 89.28 0 bottom
R638  33E  [R0402]  51.94 87.88 0 bottom
R639  33E  [R0402]  49.91 87.88 0 bottom
R640  33E  [R0402]  49.91 86.49 0 bottom
R642  0E  [R0402]  42.55 90.17 0 bottom
R643  33E  [R0402]  45.21 88.39 90 top
R644  33E  [R0402]  43.81 88.39 90 top
R645  0E  [R0402]  48.13 90.81 90 top
R646  0E  [R0402]  49.66 90.81 90 top
R647  39.2K  [R0603]  142.49 27.94 270 bottom
R648  36.5K  [R0603]  142.49 29.84 90 bottom
R649  1K  [R0402]  149.73 27.81 270 bottom
R650  10K  [R0402]  146.69 27.81 270 bottom
R651  4.7K  [R0402]  142.24 18.8 0 bottom
R652  13.7K  [R0402]  139.7 17.65 0 bottom
R653  100E  [R0402]  15.15 132.85 0 bottom
R654  0E  [R0402]  49.91 92.33 0 bottom
R655  0E  [R0402]  42.8 87 0 bottom
RN1  RPACK4-22  [RESN_EXBN8V_0402X4]  146.43 113.79 180 bottom
RN2  RPACK4-22  [RESN_EXBN8V_0402X4]  143.13 113.79 180 bottom
RN3  RPACK4-22  [RESN_EXBN8V_0402X4]  133.48 101.6 270 bottom
RN4  RPACK4-22  [RESN_EXBN8V_0402X4]  133.48 104.52 270 bottom
RN5  RPACK4-22  [RESN_EXBN8V_0402X4]  128.14 111.38 180 bottom
RN6  RPACK4-22  [RESN_EXBN8V_0402X4]  124.97 111.38 180 bottom
RN7  RPACK4-22  [RESN_EXBN8V_0402X4]  133.48 107.44 90 bottom
RN8  RPACK4-22  [RESN_EXBN8V_0402X4]  133.48 110.36 90 bottom
RN9  RPACK4-22  [RESN_EXBN8V_0402X4]  127.05 97.83 180 bottom
RST_ATTN1  EVQ-PF206K  [SW_EVQ-PF206K]  174.68 73.75 90 top
RST_BMC1  PTS635SL25SMTR LFS  [SW_PTS635SL25SMTRLFS]  117.24 144.21 180 top
RST_PWR1  EVQ-PF304R  [SW_EVQ-PF104R]  176.65 86.37 90 top
RV1  V5.5MLA0603H  [R603-35X45]  167.77 98.55 0 top
SW1  SDA04H1SBD  [SW_SDA04H1SBD]  93.65 140.72 0 top
TP1  Test Point  [TP-S40]  149.73 140.72 0 top
TP2  Test Point  [TP-S40]  116.59 137.16 180 top
TP3  Test Point  [TP-S40]  115.06 137.16 0 top
TP4  Test Point  [TP-S40]  113.54 137.16 0 top
TP5  Test Point  [TP-S40]  119.63 137.16 0 top
TP6  Test Point  [TP-S40]  118.11 137.16 0 top
TP7  Test Point  [TP-S40]  124.59 130.56 0 top
TP8  Test Point  [TP-S40]  122.94 130.81 0 top
TP9  Test Point  [TP-S40]  31.32 124.99 0 top
TP10  Test Point  [TP-S40]  114.53 119.89 270 top
TP11  Test Point  [TP-S40]  113.28 119.89 270 top
TP12  Test Point  [TP-S40]  112.14 119.89 270 top
TP13  Test Point  [TP-S40]  111 119.89 270 top
TP14  T-hole  [TP1-6040]  107.7 119.89 270 top
TP15  Test Point  [TP-S40]  107.06 111.76 270 top
TP16  Test Point  [TP-S40]  157.94 111.33 0 top
TP17  Test Point  [TP-S40]  131.83 110.87 0 top
TP18  Test Point  [TP-S40]  107.06 110.41 270 top
TP19  Test Point  [TP-S40]  131.83 109.35 0 top
TP20  Test Point  [TP-S40]  107.06 109.25 270 top
TP21  Test Point  [TP-S40]  131.83 107.7 0 top
TP22  Test Point  [TP-S40]  157.76 106.96 0 top
TP23  Test Point  [TP-S40]  131.83 106.17 0 top
TP24  Test Point  [TP-S40]  83.08 106.07 0 top
TP25  Test Point  [TP-S40]  78.33 103.25 0 top
TP26  Test Point  [TP-S40]  61.14 103.81 0 top
TP27  Test Point  [TP-S40]  116.56 101.04 270 top
TP28  Test Point  [TP-S40]  115.16 101.04 270 top
TP29  Test Point  [TP-S40]  113.77 101.04 270 top
TP30  Test Point  [TP-S40]  110.97 101.04 270 top
TP31  Test Point  [TP-S40]  109.58 101.04 270 top
TP32  Test Point  [TP-S40]  156.46 93.85 0 top
TP33  Test Point  [TP-S40]  48.01 94.11 0 top
TP34  Test Point  [TP-S40]  153.37 92.56 0 top
TP35  Test Point  [TP-S40]  152.27 92.08 270 top
TP36  Test Point  [TP-S40]  45.09 86.11 0 top
TP37  Test Point  [TP-S40]  43.94 85.72 0 top
TP38  Test Point  [TP-S40]  140.21 89.46 0 top
TP39  Test Point  [TP-S40]  27.69 83.19 0 top
TP40  Test Point  [TP-S40]  26.29 83.19 0 top
TP41  Test Point  [TP-S40]  94.59 76.97 0 top
TP42  Test Point  [TP-S40]  92.51 75.29 270 top
TP43  Test Point  [TP-S40]  92.51 74.02 270 top
TP44  Test Point  [TP-S40]  138.94 72.9 180 top
TP45  Test Point  [TP-S40]  92.51 69.48 0 top
TP46  Test Point  [TP-S40]  153.03 67.3 180 top
TP47  Test Point  [TP-S40]  92.43 63.35 180 top
TP48  Test Point  [TP-S40]  160.78 61.26 0 top
TP49  Test Point  [TP-S40]  145.75 60.33 0 top
TP50  Test Point  [TP-S40]  160.78 58.17 0 top
TP51  Test Point  [TP-S40]  72.59 36.83 270 top
TP52  Test Point  [TP-S40]  59.46 36.83 0 top
TP53  Test Point  [TP-S40]  92.79 34.77 90 top
TP54  Test Point  [TP-S40]  91.26 34.77 90 top
TP55  Test Point  [TP-S40]  90.12 34.77 90 top
TP56  Test Point  [TP-S40]  88.82 34.77 90 top
TP57  Test Point  [TP-S40]  82.37 34.65 90 top
TP58  Test Point  [TP-S40]  28.32 27.3 0 top
TP59  Test Point  [TP-S40]  79.88 31.75 90 top
TP60  Test Point  [TP-S40]  77.98 31.88 90 top
TP61  Test Point  [TP-S40]  46.86 23.62 0 top
TP62  Test Point  [TP-S40]  46.86 22.35 0 top
TP63  Test Point  [TP-S40]  99.01 22.63 0 top
TP64  Test Point  [TP_15]  53.92 84.07 180 bottom
TP65  Test Point  [TP_15]  54.99 84.07 180 bottom
TP66  Test Point  [TP28]  39.88 74.23 180 bottom
TP67  Test Point  [TP28]  39.88 72.96 180 bottom
TP68  Test Point  [TP-S40]  40.67 71.81 180 bottom
TP69  Test Point  [TP-S40]  41.3 70.74 180 bottom
TP70  Test Point  [TP_15]  68.78 68.56 180 bottom
TP71  Test Point  [TP-S40]  36.91 62.61 180 bottom
TP72  Test Point  [TP-S40]  92.58 61.34 180 bottom
TP73  Test Point  [TP-S40]  91.95 55.5 0 bottom
TP74  Test Point  [TP-S40]  38.13 54.03 180 bottom
TP75  Test Point  [TP_15]  51.98 51.76 90 bottom
TP76  Test Point  [TP_15]  51.98 53.36 90 bottom
TP77  Test Point  [TP-S40]  136.91 45.73 270 bottom
TP78  Test Point  [TP-S40]  125.12 37.03 0 bottom
TP79  Test Point  [TP-S40]  140.59 34.24 270 bottom
TP80  Test Point  [TP-S40]  88.16 32.89 180 bottom
TP81  Test Point  [TP-S40]  86.64 32.89 180 bottom
TP82  Test Point  [TP-S40]  83.85 32.89 180 bottom
TP83  Test Point  [TP-S40]  138.91 32.49 270 bottom
TP84  Test Point  [TP-S40]  110.74 31.9 0 bottom
TP85  Test Point  [TP-S40]  138.91 31.11 270 bottom
TP86  Test Point  [TP-S40]  74.76 86.08 0 top
TP87  Test Point  [TP-S40]  134.87 22.35 270 bottom
TP88  Test Point  [TP-S40]  139.7 8.57 270 bottom
TP89  Test Point  [TP-S40]  136.78 8.57 270 bottom
TP90  Test Point  [TP-S40]  136.78 7.43 270 bottom
TP91  Test Point  [TP_15]  52.38 48.16 180 bottom
TP92  Test Point  [TP-S40]  125.06 98.61 180 bottom
TP93  Test Point  [TP-S40]  74.76 89.57 0 top
TP94  Test Point  [TP-S40]  106.43 1.78 0 top
TP95  Test Point  [TP-S40]  138.56 22.61 0 top
TP96  Test Point  [TP-S40]  51.46 92.18 0 top
TP97  Test Point  [TP-S40]  51.94 88.52 0 top
U1  LM3S2D93-IQC80_0  [QFP_100P_20_630X630]  139.19 137.16 270 top
U2  CP2105  [PVQFN50P400X400_24_PWP_EINF]  162.94 135.76 180 top
U3  SN74LVC2G125DCUR  [SOIC_8P_20_79X122]  102.54 133.22 270 top
U4  UCD9090RGZT  [QFN_48P_20_276X276_TP202V25]  115.32 129.29 0 top
U5  W25X10BV  [SOIC127P600_8]  148.97 118.24 0 top
U6  SN74AUCH244RGYR  [VQFN50P450X350X100-21N_EINF]  54.69 117.93 270 top
U7  TS3L110  [QFN50P400X350_16_PWP_TI]  87 117.22 270 top
U8  MCP23S17T-E/SS  [SOIC_28P_26_402X307]  75.18 113.67 270 top
U9  XC2C64A-5-VQ44  [TQFP44]  115.32 111.63 180 top
U10  SN74AUCH244RGYR  [VQFN50P450X350X100-21N_EINF]  54.69 111.02 270 top
U11  TXS0104EPWR  [TSSOP65P640_14]  87.1 110.54 0 top
U12  SN74LVC1G04DCKR  [SC70_5P]  102.87 107.57 270 top
U13  SN74LVC1G11DCKR  [SC70_6P]  58.57 106.12 0 top
U14  SN74AUCH245RGYR  [QFN_20P_20_177X138_TP]  46.93 104.01 270 top
U15  AM1802BZWTD3  [BGA80P_16X16_361]  145.42 102.88 0 top
U16  SN74AUCH245RGYR  [QFN_20P_20_177X138_TP]  46.93 97.79 270 top
U17  CDCM6208V1RGZT  [QFN_48P_20_276X276_TP161V16]  84.3 94.87 270 top
U18  CDCM6208V1RGZT  [QFN_48P_20_276X276_TP161V16]  66.42 94.87 270 top
U19  TPS3808G33DBVR  [SOT23_6]  154.56 89.92 180 top
U20  TPS650006RTET  [QFN50P300X300X80-17N_A_EINF]  144.15 81.15 0 top
U21  TCA9517DR  [SOIC_8P_50_193X236]  18.03 79.88 90 top
U22  TPS54620RGYR  [QFN_14P_20_138X138_TP79]  155.35 70.51 90 top
U23  K2E_Processor  [SKTBGA_SS1089-RHFB-BGA080]  61.98 60.96 270 top
U24  SP3012-06UTG  [DFN50P350X135X55-14N]  171.45 60.84 270 top
U25  TPS54620RGYR  [QFN_14P_20_138X138_TP79]  143.43 57.12 270 top
U26  TPS2065CDBVR  [SOT-23_5P]  165.99 54.6 180 top
U27  SN74LVC1G07DBVR  [SOT-23_5P]  161.16 50.21 0 top
U28  TPS22913BYZVR  [DSBGA50P_0P9X0P9_4]  155.83 50.16 0 top
U29  TPS22913BYZVR  [DSBGA50P_0P9X0P9_4]  152.27 43.18 270 top
U30  SP3012-06UTG  [DFN50P350X135X55-14N]  161.67 41.13 270 bottom
U31  SN74LVC1G07DBVR  [SOT-23_5P]  149.81 34.95 270 top
U32  TPS2065CDBVR  [SOT-23_5P]  156.72 34.42 180 top
U33  LM26430  [QFN50P700X700X100-49N_C_EINF]  100.79 12.52 0 top
U34  TPS544C24  [QFN50P500X700X152-41N_EINF]  64.75 8.76 180 top
U35  LM10011SD  [WSON50P300X300X80-11N]  53.34 2.74 180 top
U36  SN74LVC1G11DCKR  [SC70_6P]  117.91 144.17 270 bottom
U37  TXB0102DCUR  [VSSOP50P310_8]  57.48 143.11 0 bottom
U38  SN74AVC4T245PWR  [SOIC_16P_26_197X252]  141.86 140.46 270 bottom
U39  MCP23S17T-E/SS  [SOIC_28P_26_402X307]  49.58 137.44 180 bottom
U40  TXS0108EPWR  [SOIC_20P_26_256X252]  61.59 136.14 270 bottom
U41  TXS0108EPWR  [SOIC_20P_26_256X252]  141.86 134.11 90 bottom
U42  SN74LVC2G157DCUT  [SOIC_8P_20_79X122]  134.49 133.6 0 bottom
U43  MCP23S17T-E/SS  [SOIC_28P_26_402X307]  84.79 130.58 270 bottom
U44  MCP23S17T-E/SS  [SOIC_28P_26_402X307]  73.79 130.43 0 bottom
U45  TXS0108EPWR  [SOIC_20P_26_256X252]  50.7 128.93 270 bottom
U46  TXS0108EPWR  [SOIC_20P_26_256X252]  61.59 128.91 270 bottom
U47  MAX3221ECPWR  [SOIC_16P_26_197X252]  155.5 127.36 270 bottom
U48  SN74LVC125APWR  [SSOP65P640_14]  164.21 128.27 270 bottom
U49  TS3L110  [QFN50P400X350_16_PWP_TI]  96.27 120.02 180 bottom
U50  MAX3221ECPWR  [SOIC_16P_26_197X252]  163.07 119.13 0 bottom
U51  SN74AUCH244RGYR  [VQFN50P450X350X100-21N_EINF]  46.86 117.6 90 bottom
U52  SN74LVC2G157DCUT  [SOIC_8P_20_79X122]  169.42 117.47 0 bottom
U53  MT29F4G08ABBDAH4D  [BGA_63P_31_512X413_C14_EINF]  64.67 114.3 90 bottom
U54  SN74AUCH244RGYR  [VQFN50P450X350X100-21N_EINF]  46.86 110.87 270 bottom
U55  SN74LVC2G125DCUR  [SOIC_8P_20_79X122]  96.06 110.82 0 bottom
U56  SN74LVC1T45DCKR  [SC70_6P]  87.12 110.49 0 bottom
U57  SN74LVC244APWR  [SOIC_20P_26_256X252]  96.8 102.23 270 bottom
U58  TXS0102DCUR  [VSSOP50P310_8]  46.91 94.34 0 bottom
U59  SN74LVC1G04DCKR  [SC70_5P]  154.56 90.42 0 bottom
U61  TLV431ACDBVR  [DBV-20X60-5]  159 82.8 0 bottom
U62  TPS22913BYZVR  [DSBGA50P_0P9X0P9_4]  25.4 77.47 180 bottom
U63  TPS22913BYZVR  [DSBGA50P_0P9X0P9_4]  83.72 69.93 0 bottom
U64  TCA9517DR  [SOIC_8P_50_193X236]  117.22 69.6 90 bottom
U65  IDT5V41068APGGI  [SOIC_16P_26_197X252]  21.03 66.42 90 bottom
U66  TCA9517DR  [SOIC_8P_50_193X236]  117.22 63.75 270 bottom
U67  PCA9306DCUR  [SOIC_8P_20_79X122]  117.22 57.78 90 bottom
U68  TXS0104EPWR  [TSSOP65P640_14]  21.46 56.01 180 bottom
U69  PCA9306DCUR  [SOIC_8P_20_79X122]  117.22 51.94 90 bottom
U70  ICS83026BGI-01LF  [TSSOP65P640_8]  21.49 50.39 0 bottom
U71  TCA9517DR  [SOIC_8P_50_193X236]  117.22 45.72 90 bottom
U72  ICS83026BGI-01LF  [TSSOP65P640_8]  21.84 43.81 0 bottom
U73  88E1514  [QFN50P800X800X100-57N]  135 38.68 270 bottom
U74  TPS51200DRCT  [QFN10P_20_118X118_TP94X65V5]  119.91 35.2 90 bottom
U75  88SE9182A2  [QFN40P700X700X90-57N_EINF]  33.57 33.81 180 bottom
U76  AT26F004  [SOIC127P600_8]  43.94 33.27 270 bottom
U77  88E1514  [QFN50P800X800X100-57N]  132.97 15.05 270 bottom
U78  MT48LC4M16A2B4-75:G  [VFBGA54C80P9X9_800X800X100_EINF]  126.77 104.47 180 bottom
U79  TXS0102DCUR  [VSSOP50P310_8]  139.95 123.19 90 bottom
U80  SN74LVC8T245RHLR  [PVQFN50P550X350X100-25N_EINF]  46.46 89.26 270 bottom
UNK0V85  Test Point  [TP-S40]  123.06 21.72 0 top
UNK1V8  Test Point  [TP-S40]  121.16 5.59 0 top
UNK3V3  Test Point  [TP-S40]  79.25 2.03 0 top
Y1  16MHz  [XTAL_ECS-120-20-3X-TR]  144.4 124.08 0 top
Y2  32.768KHz  [XTAL_SSPT7F]  160.53 105.28 0 top
Y3  24MHz  [XTAL_ABM7_1]  158.88 100.71 270 top
Y4  25 MHz  [OSC_CB3LV_3C]  54.74 99.82 270 top
Y5  ABM3B-25.000MHZ-B2-T  [XTAL_ABM3B]  54.97 92.43 270 top
Y6  ABM3B-25.000MHZ-B2-T  [XTAL_ABM3B]  22.23 30.86 90 bottom
Y7  ABM3B-25.000MHZ-B2-T  [XTAL_ABM3B]  137.03 27.64 0 bottom
Y8  ABM3B-25.000MHZ-B2-T  [XTAL_ABM3B]  135 4 0 bottom

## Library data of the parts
AMC1 = AMC_Edge_Connector
B1-B7 = 1212_FILTER_NFW31SP106X1E4L_0
C1-C100 C102 C103 C105 C106 C112-C114 C117 C120-C122 C124-C161 C163 C164 C166-C175 C177-C186 C188-C252 C254 C256 C257 C259-C433 C435-C439 C441-C479 C481-C487 C489-C506 C508-C518 C520-C532 C534-C551 C554-C564 C566-C572 C574-C576 C578-C584 C586-C594 C596-C598 C600-C606 C608 C609 C611-C633 C635-C648 C650-C661 C664-C670 C672-C683 C685-C690 C692-C768 C772-C781 C783-C866 C872 C874-C876 C881-C896 = Cap_Ceramic
C101 C104 C107-C111 C115 C116 C118 C119 C123 C162 C165 C176 C187 C573 C585 C599 C607 C610 C634 C649 C662 C769-C771 C782 = Cap_Ceramic: signal model: CAP_CERAMIC_C0402_DISCRETE_100N_100nF
C480 C488 C507 C519 C533 C552 C553 C565 C577 C595 C663 C671 C684 C691 = Cap_Ceramic: room: CPU1
CN1 CN6 = 1653_JH3X1V-2M_0
CN2 = 1654_PWR_2P_5223957-3_0
CN3 = 1653_HD_5X2P_0
CN4 = 1653_HD_2P_D_0
CN5 = 1653_JH6X1V-2M_0
CN7 = CONN_Expansion
COM1 COM2 = CONNECTOR - 3 X 1_0
CT1-CT8 = CAP POL
CVDD CVDD1 GND1-GND4 GNDC TP1-TP13 TP15-TP97 UNK0V85 UNK1V8 UNK3V3 = 00_TP-S40_0
D1 D2 = 130_SCHOTTKY_ANODE2_0
D3 = 130_LED_2P_R_KPA-1606EC_0
D4 DBG_D2 DBG_D3 = 130_LED_2P_B_KPA-1606QBC-D_0
D5 = 130_LED_LED-0603_R_0
D6 = 130_LED_LED-0603_G_0
D7-D9 = SMF-2432GC_1: Tolerance: X; User Part Number: X
